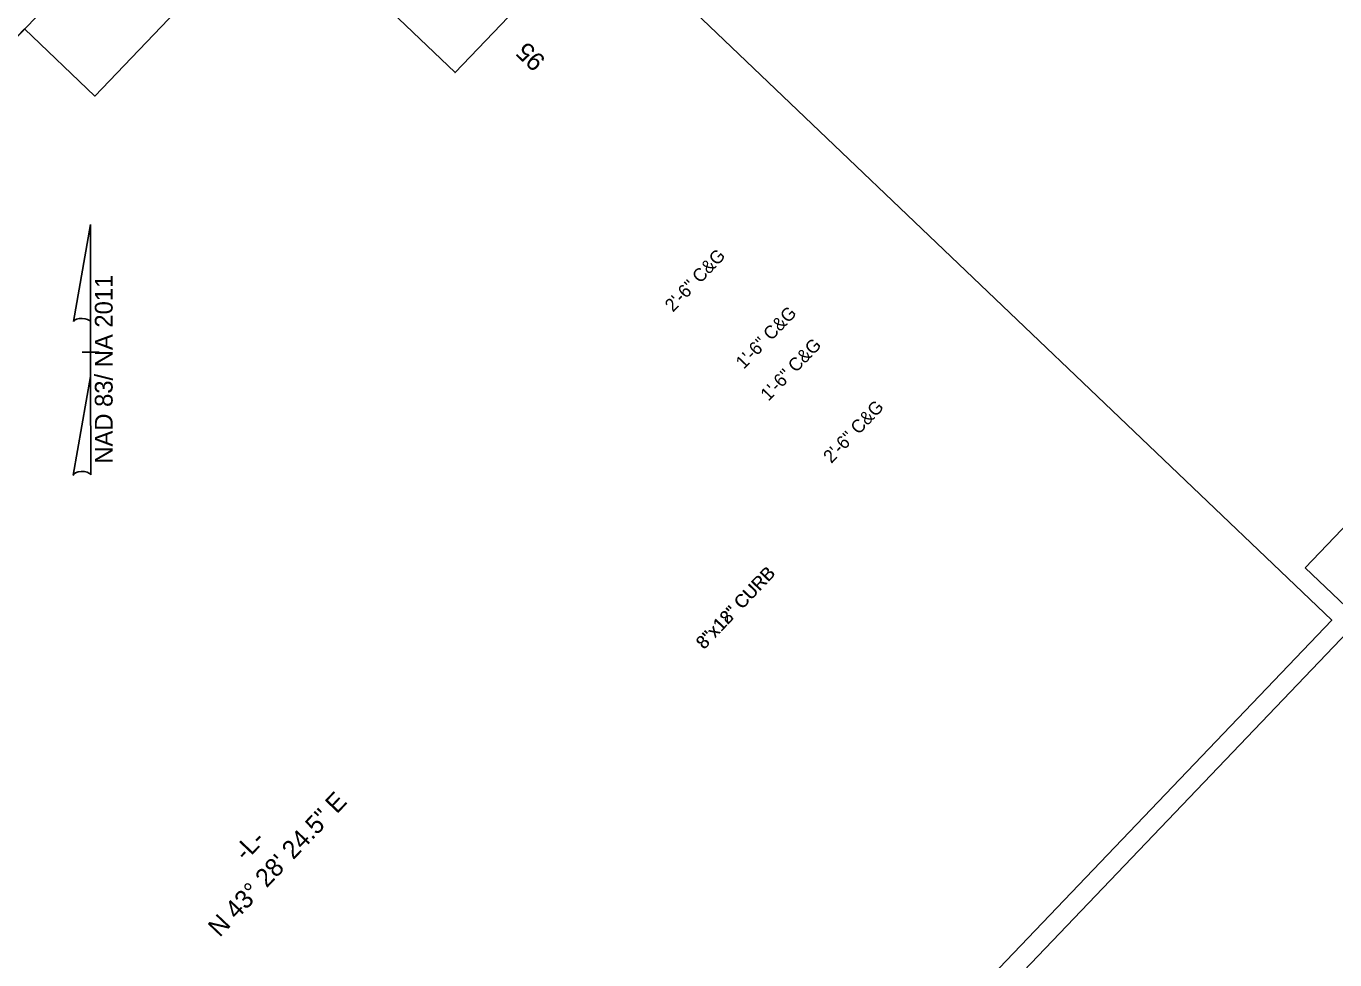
# Model space of a CAD drawing. Extents: x 2326836 to 2328631, y 602012 to 603789.
# Drawn here: x 2327551 to 2328051, y 603129 to 603486 of the extents above; entities that cross this region are included whole.
import ezdxf

# ---------------------------------------------------------------- set-up
doc = ezdxf.new("R2010")
doc.units = 0
for name, color, linetype in [('Default', 7, 'Continuous'), ('Prop Dimension Text', 7, 'Continuous'), ('Prop Horizontal Alignment Direction Label', 7, 'Continuous'), ('Prop Horizontal Alignment Tick Label', 7, 'Continuous'), ('Prop North Arrow NAD83 for Plan Sheets CELL', 7, 'Continuous'), ('Scratch_Level_1', 7, 'Continuous'), ('Sheet Plan CELL', 7, 'Continuous')]:
    doc.layers.add(name, color=color, linetype=linetype)

msp = doc.modelspace()

# ---------------------------------------------------------------- linework, layer by layer
at = {"layer": 'Default'}
msp.add_lwpolyline([(2328039.83, 603279.08), (2328231.12, 603479.27), (2328251.83, 603459.47), (2328060.55, 603259.29)], close=True, dxfattribs=at)
at = {"layer": 'Prop North Arrow NAD83 for Plan Sheets CELL'}
for p, q in [((2327568.97, 603373.33), (2327575.53, 603410.41)), ((2327575.57, 603410.41), (2327575.53, 603410.41)), ((2327575.57, 603410.41), (2327575.53, 603410.41)), ((2327575.57, 603410.41), (2327575.57, 603372.17)), ((2327575.57, 603352.33), (2327575.57, 603373.29)), ((2327575.57, 603372.17), (2327575.57, 603373.25)), ((2327572.37, 603361.61), (2327572.33, 603361.61)), ((2327575.21, 603361.61), (2327572.37, 603361.61)), ((2327572.41, 603361.61), (2327578.81, 603361.61)), ((2327575.57, 603352.33), (2327568.89, 603314.53)), ((2327575.61, 603314.69), (2327575.57, 603352.33))]:
    msp.add_line(p, q, dxfattribs=at)
for centre, start_param, end_param in [((2327572.28, 603372.93), 0.216388, 2.908219), ((2327572.28, 603314.39), 0.201328, 3.141593)]:
    msp.add_ellipse(centre, major_axis=(3.38, -0.02), ratio=0.461098, start_param=start_param, end_param=end_param, dxfattribs=at)
at = {"layer": 'Scratch_Level_1'}
msp.add_lwpolyline([(2326885.09, 602788.9), (2327620.52, 603558.61), (2327714.85, 603468.48), (2327770.17, 603526.38), (2328049.95, 603259.07), (2327259.2, 602431.46)], close=True, dxfattribs=at)
at = {"layer": 'Sheet Plan CELL'}
for points in [[(2326835.98, 602737.58), (2327550.28, 603485.23), (2327577.17, 603459.54), (2327678.48, 603565.59), (2327746, 603501.08), (2327828.41, 603587.34), (2327892.92, 603525.71), (2328031.11, 603670.36), (2328251.83, 603459.46), (2327215.55, 602374.93)], [(2327215.55, 602374.93), (2328251.82, 603459.46), (2328631.38, 603096.8), (2327595.1, 602012.27)]]:
    msp.add_lwpolyline(points, close=True, dxfattribs=at)

# ---------------------------------------------------------------- texts
at = {"layer": 'Prop Dimension Text'}
for s, rotation, p in [('2\'-6" C&G', 46.5265, (2327798.15, 603376.64)), ('2\'-6" C&G', 46.5265, (2327798.15, 603376.64)), ('1\'-6" C&G', 46.1215, (2327825.22, 603354.8)), ('1\'-6" C&G', 46.1215, (2327834.67, 603342.58)), ('2\'-6" C&G', 46.5265, (2327858.7, 603318.79)), ('8"x12" CURB', 46.5265, (2327810.01, 603247.61)), ('8"x18" CURB', 46.5265, (2327810.11, 603247.72))]:
    msp.add_text(s, height=5, rotation=rotation, dxfattribs=at).set_placement(p)
at = {"layer": 'Prop Horizontal Alignment Direction Label'}
for s, p in [('N 43%%d 28\' 24.5" E', (2327624.89, 603137.54)), ('-L-', (2327634.77, 603166.57))]:
    msp.add_text(s, height=7, rotation=46.5265, dxfattribs=at).set_placement(p)
at = {"layer": 'Prop Horizontal Alignment Tick Label'}
msp.add_text('95', height=7, rotation=136.5265, dxfattribs=at).set_placement((2327749.87, 603473.52))
at = {"layer": 'Prop North Arrow NAD83 for Plan Sheets CELL'}
msp.add_text('NAD 83/ NA 2011', height=6.8, rotation=90, dxfattribs=at).set_placement((2327583.98, 603318.92))

doc.saveas('drawing.dxf')
